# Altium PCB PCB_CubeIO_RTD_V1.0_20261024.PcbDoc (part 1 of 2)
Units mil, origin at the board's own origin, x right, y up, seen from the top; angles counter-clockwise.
Board outline 9739 x 8533 mil, 4 copper layers (TopLayer, GND, VCC, BottomLayer); 78 components, 50 nets, 272 pads, 89 vias.
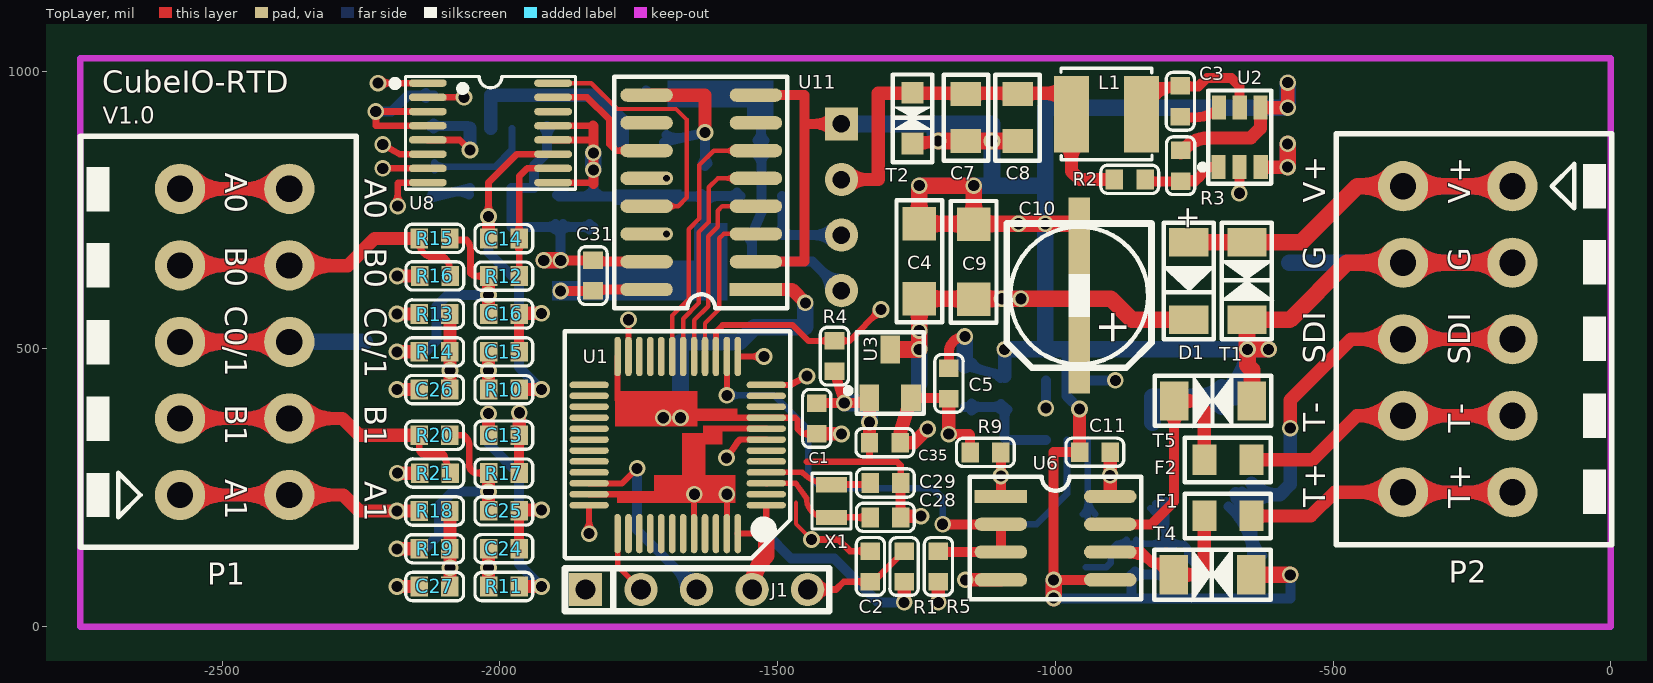
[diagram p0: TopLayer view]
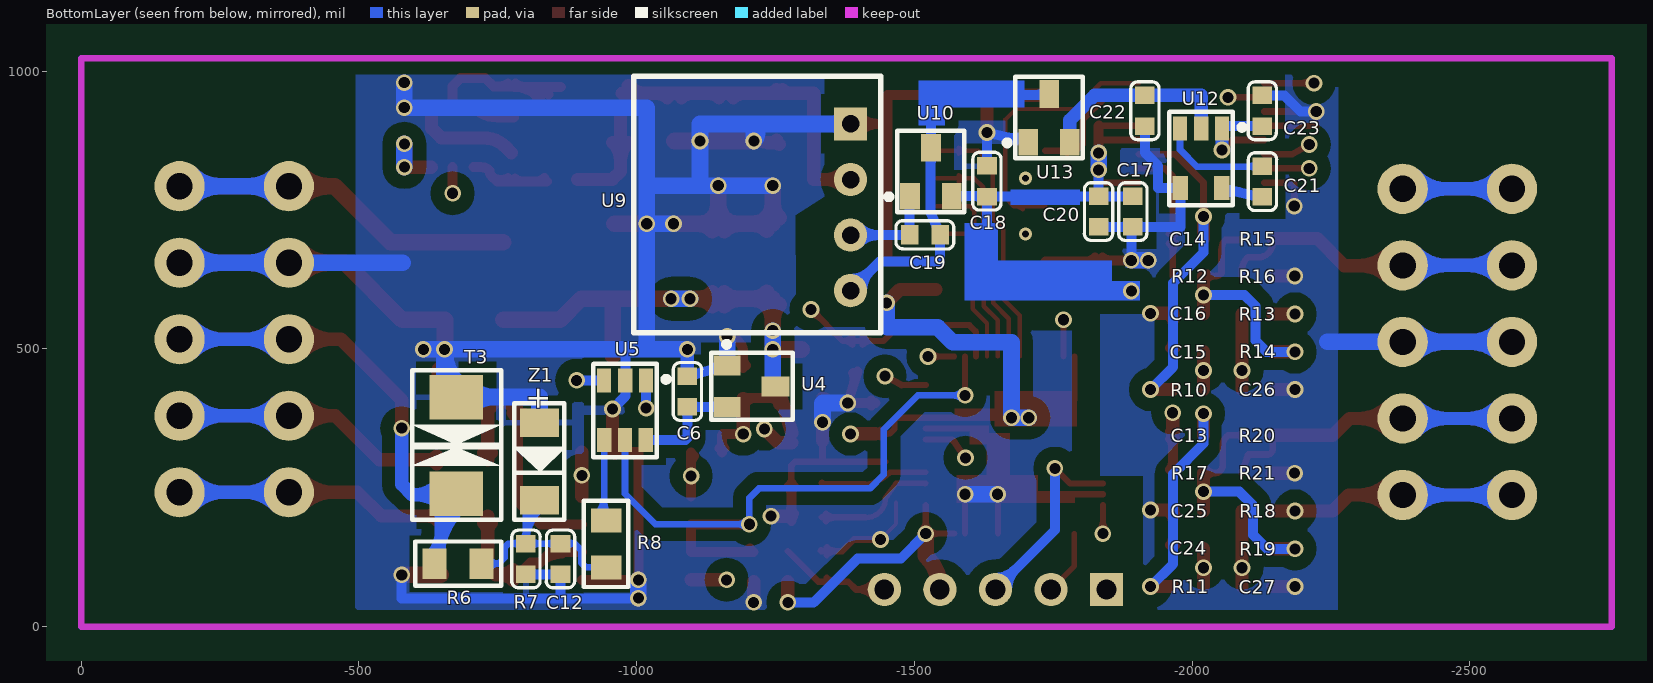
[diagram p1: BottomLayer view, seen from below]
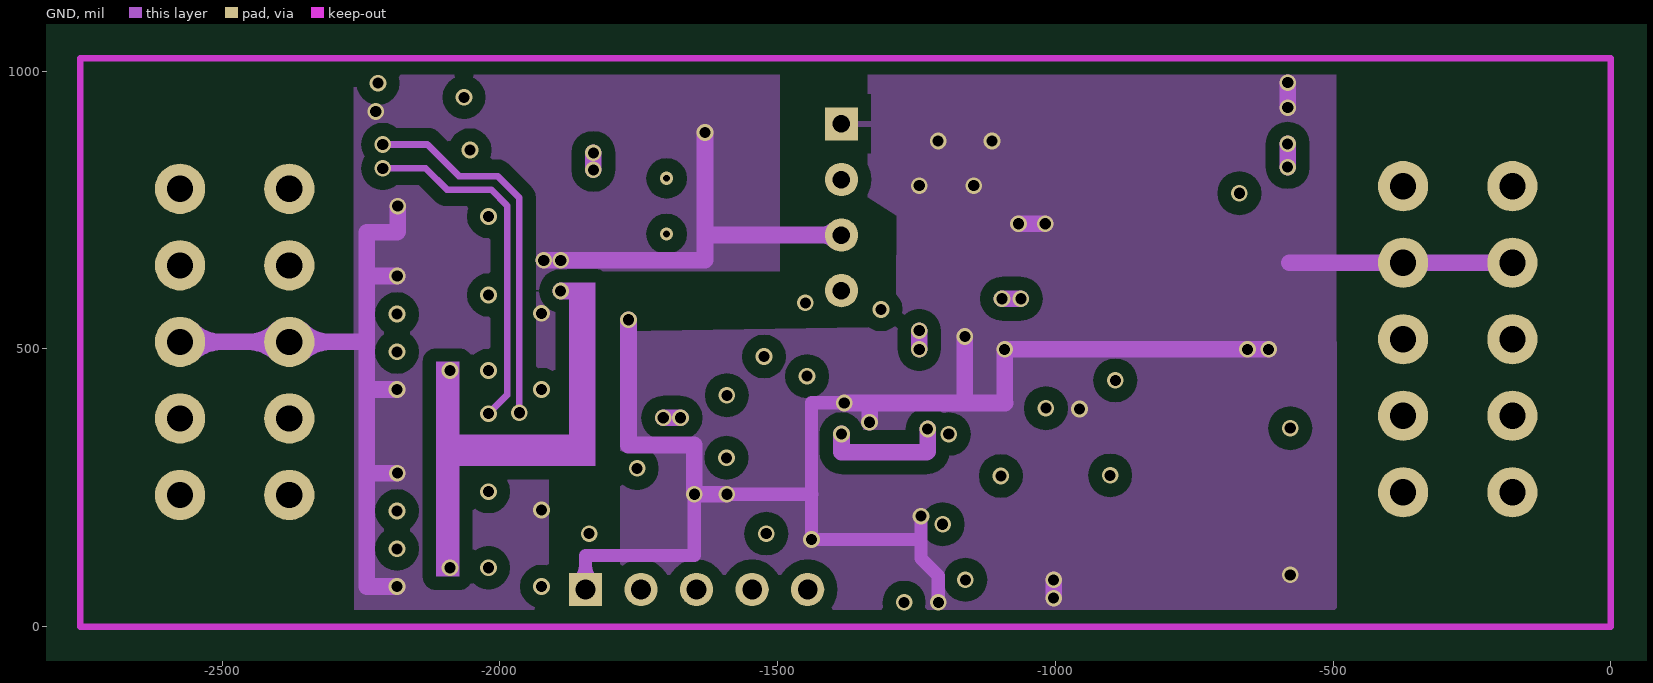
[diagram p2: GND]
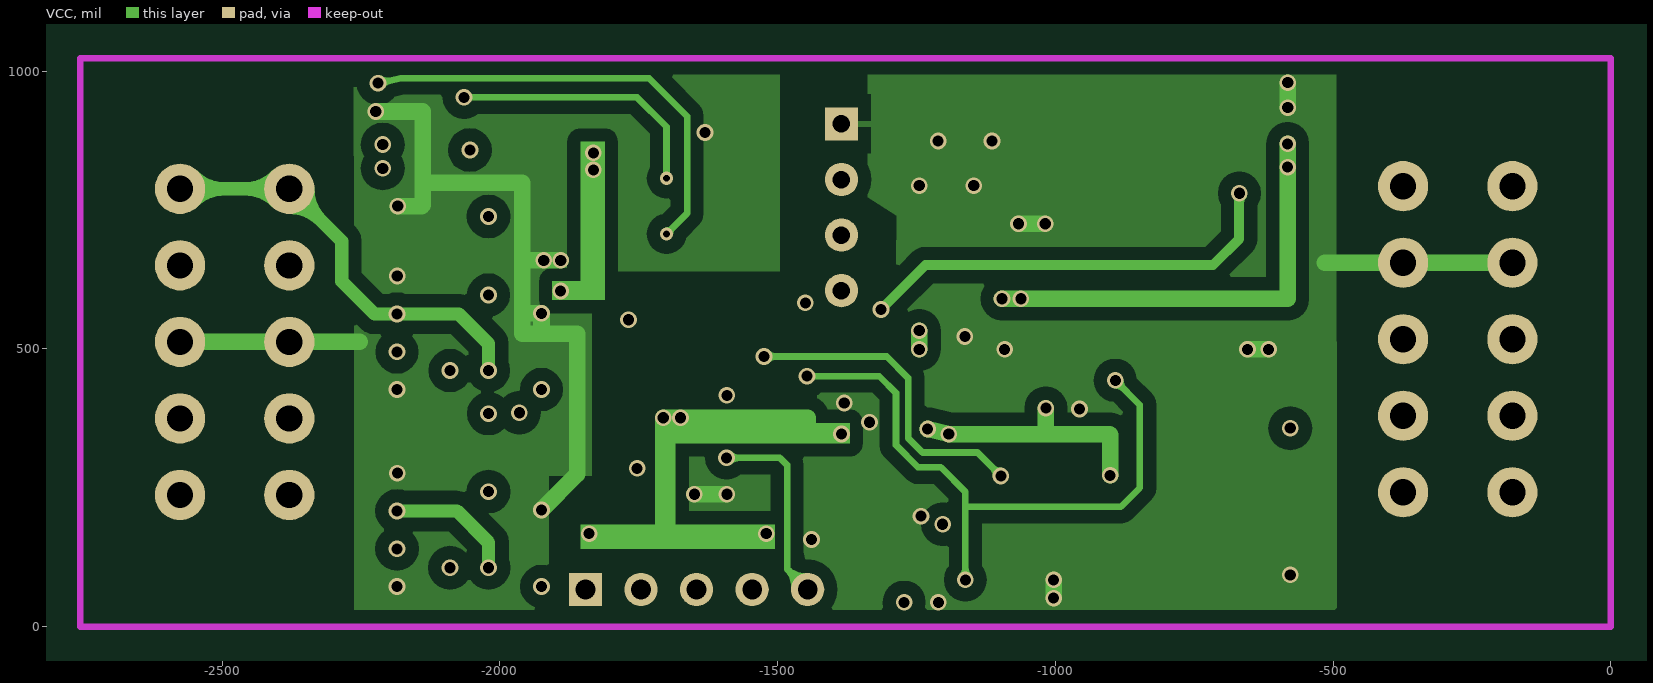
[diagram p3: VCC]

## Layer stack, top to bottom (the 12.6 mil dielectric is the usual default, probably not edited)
TopLayer: signal copper 1.4
Dielectric: core 12.6, FR-4, Dk 4.8
GND: signal copper 1.4
Dielectric: prepreg 12.6, FR-4, Dk 4.8
VCC: signal copper 1.4
Dielectric: core 12.6, FR-4, Dk 4.8
BottomLayer: signal copper 1.4

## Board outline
-5100.31,4111.96 4638.69,4111.96 4638.69,-4391.04 -5100.31,-4391.04 -5100.31,4111.96 -5070.31,4141.96

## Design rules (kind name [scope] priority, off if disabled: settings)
Clearance [All] p1: gap=24
PolygonConnect Via [IsVia] p1: connectstyle=Direct reliefconductorwidth=10 reliefentries=4 polygonreliefangle="90 Angle"
PolygonConnect [All] p2: connectstyle=Relief reliefconductorwidth=10 reliefentries=4 polygonreliefangle="90 Angle"
RoutingLayers [All] p1: top layer_v5=TRUE mid layer 1_v5=FALSE mid layer 2_v5=FALSE bottom layer_v5=TRUE
RoutingPriority [All] p1: routingpriority=4
RoutingVias [All] p1: holewidth=20 width=30 viastyle="Through Hole" minholewidth=20 minwidth=30 maxholewidth=20 maxwidth=30
SilkscreenOverComponentPads [All] p1: minsilkscreentomaskgap=10
SolderMaskExpansion [All] p1: expansion=4
TestPointUsage [All] p1: valid=0 allowmultiple=FALSE
Testpoint [All] p1: side=15 testpointundercomponent=TRUE minsize=40 maxsize=100 preferedsize=60 minholesize=20 maxholesize=40 preferedholesize=32 testpointgrid=1 style=1023 order=0-112345678
Width [All] p1: maxlimit=236.22 minlimit=6 preferedwidth=8
21 further rules are at their usual default settings.

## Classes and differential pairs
component class AI: C13 C14 C15 C16 C17 C18 C19 C20 C21 C22 C23 C24 C25 C26 C27 C31 P1 R10 R11 R12 R13 R14 R15 R16 R17 R18 R19 R20 R21 U8 U9 U10 U11 U12 U13
component class CPU: 5 5.1K 6 BT1 C1 C2 C3 C4 C5 C6 C7 C8 C9 C10 C11 C12 C28 C29 C35 COM D1 D18 D19 F1 F2 J1 JTAG1 L1 L3 P2 P6 P7 P8 PWR PWR1 Q8 R1 R2 R3 R4 R5 R6 R7 R8 R9 RUN SW6 SW7 T1 T2 T3 T4 T5 U1 U2 U3 U4 U5 U6 X1 X2 X3 Z1
component class ATTACH: ATT1 ATT2 ATT3 ATT4 ATT5 ATT6 ATT7 ATT8 ATT9

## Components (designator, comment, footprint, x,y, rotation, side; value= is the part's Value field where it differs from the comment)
C1 "100nf/50V" RC0603(1) -1429.96,347.87 r90 top
C2 "100nf/50V" RC0603(1) -1333.38,81.28 r90 top
C3 "100nf/50V" RC0603(1) -774.59,972.87 r270 top
C4 "10uf/50V" RC1206 -1244.96,590.27 r90 top
C5 "10uf/25V" RC0603(1) -1191.96,410.85 r90 top
C6 "10uf/25V" RC0603(1) -1090.96,396.27 r90 bottom
C7 "22uf/16V" RC0805 -1160.96,958.87 r270 top
C8 "22uf/16V" RC0805 -1067.96,958.87 r270 top
C9 "10uf/50V" RC1206 -1146.96,589.27 r90 top
C10 "47uf/50V" SMD-EC-F6.3 -956.96,488.27 r90 top
C11 "100nf/50V" RC0603(1) -955.96,314.27 r0 top
C12 "220pf/50V" RC0603(1) -863.25,148.78 r270 bottom
C13 "10nf/50V" RC0603(1) -2020,345 r0 top
C14 "10nf/50V" RC0603(1) -2020,699 r0 top
C15 "100nf/50V" RC0603(1) -2020,495.19 r0 top
C16 "100nf/50V" RC0603(1) -2020,563.3 r0 top
C17 "10uf/25V" RC0603(1) -1893.72,774.38 r270 bottom
C18 "100nf/50V" RC0603(1) -1631,829 r270 bottom
C19 "10uf/25V" RC0603(1) -1546,705 r0 bottom
C20 "10uf/25V" RC0603(1) -1832,774.38 r270 bottom
C21 "10uf/25V" RC0603(1) -2126.29,774.08 r90 bottom
C22 "10uf/25V" RC0603(1) -1914.63,901.8 r90 bottom
C23 "10uf/25V" RC0603(1) -2126.75,955.8 r270 bottom
C24 "100nf/50V" RC0603(1) -2020,140.64 r0 top
C25 "100nf/50V" RC0603(1) -2020,208.75 r0 top
C26 "100nf/50V" RC0603(1) -2144.5,427.08 r0 top
C27 "100nf/50V" RC0603(1) -2144.5,72.53 r0 top
C28 "6pf(+/-0.25pf)/50V,COG" RC0603(1) -1278.96,196.27 r180 top
C29 "6pf(+/-0.25pf)/50V,COG" RC0603(1) -1278.96,258.27 r180 top
C31 "100nf/50V" RC0603(1) -1832,659 r270 top
C35 "10uf/25V" RC0603(1) -1279.96,330.87 r180 top
D1 "IN5819WS" SOD-123 -759.96,692.27 r270 top
F1 "自恢复保险丝50mA/60V" RC0805 -646.96,199.27 r180 top
F2 "自恢复保险丝50mA/60V" RC0805 -646.96,300.27 r180 top
J1 "单排针,5P" SIP-5(1) -1845.96,66.87 r180 top
L1 "10uH" SMD_L4.0-W4.0_FNR40XXS -907.96,922.87 r180 top
P1 "接线焊接焊盘" KC-2604P-3.5A-5P（快接侧出线直针,淘宝:宇宙悍将旗舰店） -2576,237 r90 top locked
P2 "外部接线焊盘" KC-2604P-3.5A-5P（快接侧出线直针,淘宝:宇宙悍将旗舰店） -177,793 r270 top locked
R1 "10K,1%" RC0603(1) -1271.96,135.27 r270 top
R2 "200K,1%" RC0603(1) -838.96,804.87 r180 top
R3 "62K,1%" RC0603(1) -773.96,856.87 r270 top
R4 "200K,1%" RC0603(1) -1397.96,459.87 r90 top
R5 "10K,1%" RC0603(1) -1210.96,81.27 r90 top
R6 "510ohm,1%" RC0805 -720.96,113.27 r0 bottom
R7 "200K,1%" RC0603(1) -800.25,94.78 r90 bottom
R8 "510ohm,1%" RC0805 -944.96,191.27 r270 bottom
R9 "5.1K,1%" RC0603(1) -1098.96,313.27 r180 top
R10 "2K,0.1%" RC0603(1) -2020,427.08 r0 top
R11 "2K,0.1%" RC0603(1) -2020,72.53 r0 top
R12 "2K,0.1%" RC0603(1) -2020,631.41 r0 top
R13 "20K,0.1%" RC0603(1) -2090.44,562.42 r180 top
R14 "20K,0.1%" RC0603(1) -2090.44,494.31 r180 top
R15 "300ohm,0.1%" RC0603(1) -2090.44,698.64 r180 top
R16 "20K,0.1%" RC0603(1) -2090,631 r180 top
R17 "2K,0.1%" RC0603(1) -2020,276.86 r0 top
R18 "20K,0.1%" RC0603(1) -2090.44,207.87 r180 top
R19 "20K,0.1%" RC0603(1) -2090.44,139.76 r180 top
R20 "300ohm,0.1%" RC0603(1) -2090.44,344.09 r180 top
R21 "20K,0.1%" RC0603(1) -2089.95,276 r180 top
T1 "SMF28CA" SOD-123-TVS -654.96,692.27 r270 top
T2 "GBLC05C" SOD-323-ESD-GBLCxx/UDD32CxxL01(1) -1257,961.1 r270 top
T3 "SMBJ28CA" "DO-214AA(SMB) -TVS" -674.96,239.27 r90 bottom
T4 "SMF6.5CA" SOD-123-TVS -786.96,93.27 r0 top
T5 "SMF6.5CA" SOD-123-TVS -785.96,406.27 r0 top
U1 "STM32L072CZT7" LQFP48_N -1679.96,326.87 r180 top
U2 "AP63200WU-7(ADJ)" SOT23-6(WIDEPAD) -705.96,827.27 r0 top
U3 "HT7533S" SOT23-3(1) -1334.96,411.87 r0 top
U4 "HT7550S" SOT23-3(1) -1162.96,470.27 r270 bottom
U5 "74LVC1T45DBVR" SOT23-6(WIDEPAD) -1016.96,443.27 r0 bottom
U6 "TP8485E-SR" SO-8-150mil -1097.96,234.27 r0 top
U8 "ADS1220IPWR" TSSOP-16_L5.0-W4.4-P0.65-LS6.4-BL -2017,889 r270 top
U9 "B0303S-1WR2(德旭电子)" MORSUN_B_S_1W-LAY -1385,905 r270 bottom
U10 "AP2210N-3.3TRG1" SOT23-3(1) -1492,775 r180 bottom
U11 "PAI-141U31" SO-16 -1539,607 r180 top
U12 "TPS60400DBVR" SOT23-5(WIDEPAD) -2054,897 r0 bottom
U13 "AP2210N-2.5TRE1" SOT23-3(1) -1705,872 r180 bottom
X1 "32.768kHz" OSC-2012-2P-SMD -1402.96,225.87 r270 top
Z1 "MMSZ4693(7.5V稳压管)" SOD-123 -824.96,367.27 r270 bottom

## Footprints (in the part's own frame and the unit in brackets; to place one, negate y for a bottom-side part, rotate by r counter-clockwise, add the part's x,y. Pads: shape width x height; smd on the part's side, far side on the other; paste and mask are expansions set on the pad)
"DO-214AA(SMB) -TVS" [mil]
  rect 80x96 smd: 1(0,0) 2(174,0)
  silkscreen extent -47,-82 222,80
KC-2604P-3.5A-5P（快接侧出线直针,淘宝:宇宙悍将旗舰店） [mm] "淘宝pokerface0411订单号: 5057329177195112327,宇宙悍将旗舰店"
  round 2.3 hole 1.2: 1(0,0) 1(0,-5) 2(3.5,-5) 2(3.5,0) 3(7,-5) 3(7,0) 4(10.5,-5) 4(10.5,0) 5(14,-5) 5(14,0)
  silkscreen extent -2.4,-8.05 16.4,4.55
LQFP48_N [mm] "Thin QFP, 48-Leads, Body 7x7mm, Pitch 0.5mm, IPC Medium Density"
  oval 1.8x0.3 smd: 1(-4.05,2.75) 2(-4.05,2.25) 3(-4.05,1.75) 4(-4.05,1.25) 5(-4.05,0.75) 6(-4.05,0.25) 7(-4.05,-0.25) 8(-4.05,-0.75) 9(-4.05,-1.25) 10(-4.05,-1.75) 11(-4.05,-2.25) 12(-4.05,-2.75) 25(4.05,-2.75) 26(4.05,-2.25) 27(4.05,-1.75) 28(4.05,-1.25) 29(4.05,-0.75) 30(4.05,-0.25) 31(4.05,0.25) 32(4.05,0.75) 33(4.05,1.25) 34(4.05,1.75) 35(4.05,2.25) 36(4.05,2.75)
  oval 0.3x1.8 smd: 13(-2.75,-4.05) 14(-2.25,-4.05) 15(-1.75,-4.05) 16(-1.25,-4.05) 17(-0.75,-4.05) 18(-0.25,-4.05) 19(0.25,-4.05) 20(0.75,-4.05) 21(1.25,-4.05) 22(1.75,-4.05) 23(2.25,-4.05) 24(2.75,-4.05) 37(2.75,4.05) 38(2.25,4.05) 39(1.75,4.05) 40(1.25,4.05) 41(0.75,4.05) 42(0.25,4.05) 43(-0.25,4.05) 44(-0.75,4.05) 45(-1.25,4.05) 46(-1.75,4.05) 47(-2.25,4.05) 48(-2.75,4.05)
  silkscreen extent -5.16,-5.21 5.16,5.18
MORSUN_B_S_1W-LAY [mil]
  rect 60x60 hole 31.5: 1(0,0)
  round 60 hole 31.5: 2(100,0) 3(200,0) 4(300,0)
  silkscreen extent -86,-390 376,55
OSC-2012-2P-SMD [mm]
  rect 0.7x1.4 smd: 1(-0.75,0) 2(0.75,0)
  silkscreen extent -1.27,-0.89 1.27,0.89
RC0603(1) [mm]
  rect 0.8x0.9 smd: 1(-0.013,-0.007) 2(1.387,-0.007)
  silkscreen extent -0.64,-0.66 2.01,0.64
RC0805 [mm]
  rect 1.1x1.4 smd: 1(0,0) 2(2.15,0)
  silkscreen extent -0.89,-1.02 3.05,1.02
RC1206 [mil] "1/4W 3.2X1.6"
  rect 60x60 smd: 1(0,0) 2(135,0)
  silkscreen extent -42,-41 177,41
SIP-5(1) [mil]
  rect 60x60 hole 35.43: 1(0,0)
  round 60 hole 35.43: 2(-100,0) 3(-200,0) 4(-300,0) 5(-400,0)
  silkscreen extent -439,-38 37,39
SMD-EC-F6.3 [mm]
  rect 3.5x1 smd: 1(0,0) 2(5.475,0)
  silkscreen extent -0.56,-3.31 6.04,3.31
SMD_L4.0-W4.0_FNR40XXS [mm]
  rect 1.6x3.5 smd: 1(-1.6,0) 2(1.6,0)
  silkscreen extent -2.08,-2.1 2.08,2.1
SO-8-150mil [mm]
  rect 2.4x0.61 smd: 1(0,0)
  oval 2.4x0.61 smd: 2(0,-1.27) 3(0,-2.54) 4(0,-3.81) 5(5,-3.81) 6(5,-2.54) 7(5,-1.27) 8(5,0)
  silkscreen extent -1.42,-4.7 6.43,0.89
SO-16 [mm]
  rect 2.4x0.61 smd: 1(0,0)
  oval 2.4x0.61 smd: 2(0,-1.27) 3(0,-2.54) 4(0,-3.81) 5(0,-5.08) 6(0,-6.35) 7(0,-7.62) 8(0,-8.89) 9(5,-8.89) 10(5,-7.62) 11(5,-6.35) 12(5,-5.08) 13(5,-3.81) 14(5,-2.54) 15(5,-1.27) 16(5.004,0)
  silkscreen extent -1.42,-9.73 6.48,0.85
SOD-123 [mm]
  rect 1.3x1.8 smd: 1(0,0) 2(3.556,0)
  silkscreen extent -0.89,-1.22 4.44,1.22
SOD-123-TVS [mm]
  rect 1.3x1.8 smd: 1(0,0) 2(3.556,0)
  silkscreen extent -0.89,-1.24 4.44,1.24
SOD-323-ESD-GBLCxx/UDD32CxxL01(1) [mm]
  rect 1x1 smd: 1(0,0) 2(2.32,0)
  silkscreen extent -0.84,-0.91 3.17,0.9
SOT23-3(1) [mm]
  rect 0.9x1.2 smd: 1(0,0) 2(1.905,0)
  rect 0.9x1.27 smd: 3(0.965,2.21)
  silkscreen extent -1.09,-0.74 2.49,3
SOT23-5(WIDEPAD) [mm]
  rect 0.65x1.1 smd: 1(0,0) 2(0.95,0) 3(1.925,0)
  rect 0.7x1.1 smd: 4(1.912,2.723) 5(0.012,2.723)
  silkscreen extent -1.04,-0.76 2.41,3.51
SOT23-6(WIDEPAD) [mm]
  rect 0.65x1.1 smd: 1(0,0) 2(0.95,0) 3(1.925,0) 4(1.912,2.723) 5(0.965,2.718) 6(0.012,2.723)
  silkscreen extent -0.86,-0.76 2.41,3.51
TSSOP-16_L5.0-W4.4-P0.65-LS6.4-BL [mil]
  oval 13.5x68.17 smd paste+2: 1(-89.57,-112.82) 2(-63.98,-112.82) 3(-38.39,-112.82) 4(-12.79,-112.82) 5(12.8,-112.82) 6(38.39,-112.82) 7(63.98,-112.82) 8(89.57,-112.82) 9(89.57,112.83) 10(63.98,112.83) 11(38.39,112.83) 12(12.8,112.83) 13(-12.79,112.83) 14(-38.39,112.83) 15(-63.98,112.83) 16(-89.57,112.83)
  silkscreen extent -101,-178 101,153

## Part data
C1 C2 C3 C11 C15 C16 C18 C24 C25 C26 C27 C31: library part CAP, "电容,100nf/50V,贴片,0603"
C4 C9: library part CAPACITOR_POL, "电容,10uf/50V,贴片,1206"
C5: library part ELECTRO1, "电容,10uf/25V,贴片,0805"
C6 C19 C20 C35: library part CAP, "电容,10uf/25V,贴片,0805"
C7 C8: library part ELECTRO1, "电容,22uf/16V,贴片,0805"
C10: library part CAPACITOR_POL, "电解电容,47uf/50V,贴片,D6.3L5.4"
C12: library part CAP, "电容,220pf/50V,贴片,0603"
C13 C14: library part CAP, "电容,10nf/50V,贴片,0603"
C17 C21 C22 C23: library part CAP, "电容,10uf/25V,贴片,0603"
C28 C29: library part CAP, "电容,6pf(+/-0.25pf)/50V,COG,贴片,0603"
D1: library part DIODE, "肖特基二极管,IN5819WS,贴片,SOD-123(1206)"
F1 F2: library part FUSE, "自恢复保险丝,自恢复保险丝50mA/60V,贴片,1206"
J1: library part "Header 5", "插针,单排针,直插,2.54MM间距,针高11MM,5P"
L1: library part INDUCTOR, "功率电感,10uH,20%,FHD4020S-100MT,贴片,SMD,4*4*2mm"
P1 P2: library part MHDR1X5, "Header, 5-Pin"
R1: library part RES_1, "电阻,10K,1%,贴片,0603"
R2 R4 R7: library part RESISTOR, "电阻,200K,1%,贴片,0603"
R3: library part RESISTOR, "电阻,62K,1%,贴片,0603"
R5: library part RESISTOR, "电阻,10K,1%,贴片,0603"
R6 R8: library part RESISTOR, "电阻,510ohm,1%,贴片,0805"
R9: library part RESISTOR, "电阻,5.1K,1%,贴片,0603"
R10 R11 R12 R17: library part RESISTOR, "电阻,2K,0.1%,贴片,0603"
R13 R14 R16 R18 R19 R21: library part RESISTOR, "电阻,20K,0.1%,贴片,0603"
R15 R20: library part RESISTOR, "电阻,300ohm,0.1%,贴片,0603"
T1 T3: library part TVS, "抗雷击二极管,SMF28CA,贴片,SOD-123"
T2: library part TVS, "抗雷击二极管,GBLC05C,贴片,SOD-323"
T4 T5: library part TVS, "抗雷击二极管,SMF6.5CA,贴片,SOD-123"
U1: library part STM32L051C8T6
U2: library part SCT2332(DC/DC), "电源,AP63200WU-7(ADJ),贴片,TSOT23-6L"
U3: library part HT7530S(UMW友台半导体), "电源,ME6203A33M3G(LDO,40V输入,3.3V输出),贴片,SOT-23"
U4: library part HT7530S(UMW友台半导体), "电源,ME6203A50M3G(LDO,40V输入,5V输出),贴片,SOT-23"
U5: library part 74LVC1T45, "74系列,74LVC1T45DBVR,贴片,SOT-23-6"
U6: library part MAX485, "RS485通讯,TP8485E-SR,贴片,SO-8"
U8: "AD转换器,ADS1220IPWR(24位AD转换),贴片,TSSOP-16"
U9: library part MORSUN_B0505S_1W, "电源DCDC,B0303S-1WR2(德旭电子),直插,SIP"
U10: library part HT7530S(UMW友台半导体), "电源,AP2210N-3.3TRG1(DIODES美台),贴片,SOT-23"
U11: "光耦,PAI-141U31,贴片,SO-16"
U12: library part TPS60400, "电源,TPS60400DBVR,贴片,SOT-23-5"
U13: library part HT7530S(UMW友台半导体), "电源,AP2210N-2.5TRE1(DIODES美台),贴片,SOT-23"
X1: library part XTAL, "晶振,SC-20S(32.768kHz,20PPM,7pF, Seiko精工),贴片,SMD-2012-2P"
Z1: library part ZENER, "稳压二极管,MMSZ4693(7.5V稳压管),贴片,SOD-123"

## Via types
v1: diameter 30, hole 20, TopLayer to BottomLayer, 87 vias
v2: diameter 24, hole 12, TopLayer to BottomLayer, 2 vias

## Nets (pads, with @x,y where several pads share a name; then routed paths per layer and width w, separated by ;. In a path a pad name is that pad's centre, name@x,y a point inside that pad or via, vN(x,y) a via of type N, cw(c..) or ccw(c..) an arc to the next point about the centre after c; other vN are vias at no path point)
+3V5: C7.1 C8.1 L1.2 R2.2 T2.1 U9.2 | length 1426.5
  TopLayer w24: U9.2@-1385,805 -1319,805 -1319,960 -1318.9,960.1 -1257,960.1 L1.2@-974,960.1 ; L1.2@-970.95,922.87 -970.95,819.95 -956.16,805.16 R2.2@-893.58,805.16 ; -1341.54,805 cw(c-1341.54,848.46) -1372.27,817.73 ccw(c-1341.54,848.46) -1341.54,805 ; -1341.54,805 ccw(c-1341.54,761.54) -1372.27,792.27 cw(c-1341.54,761.54) -1341.54,805 ; -970.95,838.4 cw(c-923.88,838.4) -957.16,871.69 ccw(c-923.88,838.4) -970.95,838.4 ; -970.95,838.4 ccw(c-1018.02,838.4) -984.74,871.69 cw(c-1018.02,838.4) -970.95,838.4 ; -1277.97,960.1 ccw(c-1277.97,982.07) -1262.43,966.54 cw(c-1277.97,982.07) -1277.97,960.1 ; T2.1@-1251.57,966.54 ccw(c-1236.03,982.07) -1236.03,960.1 cw(c-1236.03,982.07) T2.1@-1251.57,966.54 ; -1193.14,960.1 cw(c-1193.14,932.6) -1173.69,952.05 ccw(c-1193.14,932.6) -1193.14,960.1 ; C7.1@-1148.23,952.05 cw(c-1128.78,932.6) -1128.78,960.1 ccw(c-1128.78,932.6) C7.1@-1148.23,952.05 ; -1100.14,960.1 cw(c-1100.14,932.6) -1080.69,952.05 ccw(c-1100.14,932.6) -1100.14,960.1 ; C8.1@-1055.23,952.05 cw(c-1035.78,932.6) -1035.78,960.1 ccw(c-1035.78,932.6) C8.1@-1055.23,952.05 ; -1018.43,960.1 ccw(c-1018.43,1007.76) -984.74,974.06 cw(c-1018.43,1007.76) -1018.43,960.1 ; -1017.6,960.1 cw(c-1017.6,913.62) -984.74,946.49 ccw(c-1017.6,913.62) -1017.6,960.1
+5V: C6.1 U4.2 U5.6 | length 368.3
  BottomLayer w18: U4.2@-1162.96,395.27 -1162.46,395.78 C6.1@-1091.25,395.78 -1091.25,339.33 ; -1087.98,336.06 U5.6@-1016.49,336.06 ; -1109.51,395.78 cw(c-1109.51,379.49) -1097.99,391.01 ccw(c-1109.51,379.49) -1109.51,395.78 ; -1109.51,395.78 ccw(c-1109.51,412.07) -1097.99,400.55 cw(c-1109.51,412.07) -1109.51,395.78 ; -1091.25,379.49 cw(c-1074.96,379.49) -1086.48,391.01 ccw(c-1074.96,379.49) -1091.25,379.49 ; -1091.25,379.49 ccw(c-1107.54,379.49) -1096.02,391.01 cw(c-1107.54,379.49) -1091.25,379.49 ; U4.2@-1150.89,389.11 cw(c-1134.8,373.02) -1134.8,395.78 ccw(c-1134.8,373.02) U4.2@-1150.89,389.11 ; U4.2@-1150.89,401.44 ccw(c-1137.22,415.1) -1137.22,395.78 cw(c-1137.22,415.1) U4.2@-1150.89,401.44
+24V: C4.1 C9.1 C10.1 D1.2 U2.3 U3.3 U4.3 | length 2907.4
  TopLayer w24: U2.3@-630.16,827.27 v1(-581.73,827.27)
  TopLayer w30: U3.3@-1296.96,498.87 -1245.36,498.87 v1(-1244.96,499.27) ; v1@-1244.96,501.27 C4.1@-1244.96,590.27 -1031.96,590.27 -899.96,590.27 -861.96,552.27 -836.96,552.27 D1.2@-759.96,552.27 ; C10.1@-956.96,488.27 -956.96,587.31 -954,590.27 ; v1(-581.73,827.27) v1(-581.73,869.27) ; -1244.96,554.06 cw(c-1208.75,554.06) C4.1@-1234.35,579.67 ; -1244.96,554.06 ccw(c-1281.17,554.06) -1255.57,579.67 cw(c-1281.17,554.06) -1244.96,554.06 ; -1244.96,554.06 cw(c-1208.75,554.06) C4.1@-1234.35,579.67 ; C4.1@-1234.35,579.67 cw(c-1208.75,554.06) -1208.75,590.27 ; C4.1@-1234.35,579.67 cw(c-1208.75,554.06) -1208.75,590.27 ; -1208.75,590.27 cw(c-1208.75,626.49) -1234.35,600.88 ccw(c-1208.75,626.49) -1208.75,590.27 ; -1185.59,590.27 cw(c-1185.59,550.65) -1157.57,578.67 ccw(c-1185.59,550.65) -1185.59,590.27 ; -1180.76,590.27 ccw(c-1180.76,623.07) -1157.57,599.88 cw(c-1180.76,623.07) -1180.76,590.27 ; C9.1@-1136.35,578.67 cw(c-1108.33,550.65) -1108.33,590.27 ccw(c-1108.33,550.65) C9.1@-1136.35,578.67 ; C9.1@-1136.35,599.88 ccw(c-1113.16,623.07) -1113.16,590.27 cw(c-1113.16,623.07) C9.1@-1136.35,599.88
  GND w30: v1(-1244.96,499.27) v1(-1244.96,532.87) ; v1(-1096,590.27) v1(-1062,590.27) ; v1(-581.73,827.27) v1(-581.73,869.27)
  VCC w30: v1(-1244.96,499.27) v1(-1244.96,532.87) ; -587.27,590.27 v1(-1096,590.27) -581.73,590.27 v1(-581.73,827.27) v1(-581.73,869.27)
  BottomLayer w30: U4.3@-1244.96,437.27 v1(-1244.96,499.27) v1(-1244.96,532.87) ; v1(-1096,590.27) v1(-1062,590.27) ; v1(-581.73,827.27) v1(-581.73,869.27)
+24X: D1.1 P2.1 T1.1 | length 1740
  TopLayer w30: D1.1@-759.96,692.27 T1.1@-654.96,692.27 -556.73,692.27 -456,793 P2.1@-177,793 ; -446.94,793 cw(c-446.94,719.91) -395.26,771.59 ccw(c-446.94,719.91) -446.94,793 ; -446.94,793 ccw(c-446.94,866.09) -395.26,814.41 cw(c-446.94,866.09) -446.94,793 ; -300.76,793 cw(c-300.76,866.09) -352.44,814.41 ccw(c-300.76,866.09) -300.76,793 ; -300.76,793 ccw(c-300.76,719.91) -352.44,771.59 cw(c-300.76,719.91) -300.76,793 ; -250.09,793 cw(c-250.09,719.91) -198.41,771.59 ccw(c-250.09,719.91) -250.09,793 ; -250.09,793 ccw(c-250.09,866.09) -198.41,814.41 cw(c-250.09,866.09) -250.09,793
  BottomLayer w30: P2.1@-373.85,793 P2.1@-177,793 ; P2.1@-352.44,771.59 cw(c-300.76,719.91) -300.76,793 cw(c-300.76,866.09) P2.1@-352.44,814.41 ; P2.1@-198.41,771.59 ccw(c-250.09,719.91) -250.09,793 ccw(c-250.09,866.09) P2.1@-198.41,814.41
A: F1.2 T4.1 U6.6 | length 680.4
  TopLayer w18: U6.6@-901.11,134.27 -844.96,134.27 -825.96,115.27 ; T4.1@-786.96,93.27 -808.96,115.27 -825.96,115.27 ; -825.96,115.27 cw(c-825.96,91.04) -802.81,98.21 ccw(c-825.96,91.04) -825.96,115.27 ; U6.6@-865.87,131.27 cw(c-865.87,73.56) -825.06,114.37 ccw(c-865.87,73.56) U6.6@-865.87,131.27 ; U6.6@-864.99,131.41 cw(c-856.05,102.28) -834.51,123.82 ccw(c-856.05,102.28) U6.6@-864.99,131.41
  TopLayer w24: T4.1@-786.96,93.27 -745.96,93.27 -731.61,107.63 F1.2@-731.61,199.27 F1.2@-730.37,198.04 ; -754.15,93.27 cw(c-754.15,126.08) -777.35,102.88 ccw(c-754.15,126.08) -754.15,93.27 ; -754.15,93.27 ccw(c-754.15,60.46) -777.35,83.66 cw(c-754.15,60.46) -754.15,93.27 ; -731.61,170.06 cw(c-708.3,170.06) -724.78,186.54 ccw(c-708.3,170.06) -731.61,170.06 ; -731.61,170.06 ccw(c-754.91,170.06) -738.43,186.54 cw(c-754.91,170.06) -731.61,170.06
A0: C15.1 P1.5 R10.1 R13.2 | length 2545.5
  TopLayer w24: P1.5@-2576,788.18 P1.5@-2379.15,788.18 ; P1.5@-2552.47,764.65 cw(c-2495.67,707.85) -2495.67,788.18 cw(c-2495.67,868.52) P1.5@-2552.47,811.71 ; P1.5@-2402.68,764.65 ccw(c-2459.48,707.85) -2459.48,788.18 ccw(c-2459.48,868.52) P1.5@-2402.68,811.71 ; v1(-2185.23,562.71) R13.2@-2145.06,562.71 ; R10.1@-2020.5,426.79 C15.1@-2020.5,494.9
  VCC w24: P1.5@-2576,788.18 P1.5@-2379.15,788.18 ; P1.5@-2359.18,788.18 P1.5@-2379.15,788.18 ; v1(-2020.5,461) -2020.5,509.5 -2073.71,562.71 v1(-2185.23,562.71) -2225.71,562.71 -2285,622 -2285,694.03 P1.5@-2379.15,788.18 ; -2495.67,788.18 cw(c-2495.67,868.52) -2552.47,811.71 ccw(c-2495.67,868.52) -2495.67,788.18 ; -2495.67,788.18 ccw(c-2495.67,707.85) -2552.47,764.65 cw(c-2495.67,707.85) -2495.67,788.18 ; -2459.48,788.18 cw(c-2459.48,707.85) -2402.68,764.65 ccw(c-2459.48,707.85) -2459.48,788.18 ; -2459.48,788.18 ccw(c-2459.48,868.52) -2402.68,811.71 cw(c-2459.48,868.52) -2459.48,788.18 ; -2322.34,731.38 cw(c-2265.54,788.18) -2345.87,788.18 ccw(c-2265.54,788.18) -2322.34,731.38 ; -2322.34,731.38 ccw(c-2379.15,674.57) -2379.15,754.91 cw(c-2379.15,674.57) -2322.34,731.38
  BottomLayer w24: P1.5@-2576,788.18 P1.5@-2379.15,788.18 ; P1.5@-2552.47,764.65 cw(c-2495.67,707.85) -2495.67,788.18 cw(c-2495.67,868.52) P1.5@-2552.47,811.71 ; P1.5@-2402.68,764.65 ccw(c-2459.48,707.85) -2459.48,788.18 ccw(c-2459.48,868.52) P1.5@-2402.68,811.71
A1: C24.1 P1.1 R11.1 R18.2 | length 1951.1
  TopLayer w24: P1.1@-2576,237 -2282,237 -2253.16,208.16 v1(-2185.23,208.16) R18.2@-2145.06,208.16 ; R11.1@-2020.5,72.24 C24.1@-2020.5,140.35 ; -2495.67,237 cw(c-2495.67,317.33) -2552.47,260.53 ccw(c-2495.67,317.33) -2495.67,237 ; -2495.67,237 ccw(c-2495.67,156.67) -2552.47,213.47 cw(c-2495.67,156.67) -2495.67,237 ; -2459.48,237 cw(c-2459.48,156.67) -2402.68,213.47 ccw(c-2459.48,156.67) -2459.48,237 ; -2459.48,237 ccw(c-2459.48,317.33) -2402.68,260.53 cw(c-2459.48,317.33) -2459.48,237 ; -2298.82,237 cw(c-2298.82,317.33) -2355.62,260.53 ccw(c-2298.82,317.33) -2298.82,237 ; -2298.82,237 ccw(c-2298.82,156.67) -2355.62,213.47 cw(c-2298.82,156.67) -2298.82,237
  VCC w24: v1(-2185.23,208.16) -2077.16,208.16 -2020.5,151.5 v1(-2020.5,106)
  BottomLayer w24: P1.1@-2576,237 P1.1@-2379.15,237 ; P1.1@-2552.47,213.47 cw(c-2495.67,156.67) -2495.67,237 cw(c-2495.67,317.33) P1.1@-2552.47,260.53 ; P1.1@-2402.68,213.47 ccw(c-2459.48,156.67) -2459.48,237 ccw(c-2459.48,317.33) P1.1@-2402.68,260.53
ADC_CS: U8.2 U11.12 | length 544.8
  TopLayer w12: U8.2@-2129.82,952.98 v1(-2064.63,952.98)
  VCC w12: v1(-2064.63,952.98) -1752.98,952.98 -1700,900 v2(-1700,807)
ADC_DIN: U8.16 U11.13 | length 547.1
  TopLayer w8: U8.16@-1904.17,978.57 -1835.57,978.57 -1789,932 -1683,932 -1664,913 -1664,772 -1679,757 U11.13@-1735.85,757 ; -1681.29,757 cw(c-1681.29,776.31) -1694.95,762.66 ccw(c-1681.29,776.31) -1681.29,757 ; -1681.29,757 ccw(c-1681.29,737.69) -1694.95,751.34 cw(c-1681.29,737.69) -1681.29,757
ADC_DOUT_DRDY: U8.15 U11.11 | length 279.4
  TopLayer w12: U8.15@-1904.17,952.98 -1842.98,952.98 -1803,913 -1803,868.92 -1791.08,857 U11.11@-1735.85,857 ; -1785.58,857 cw(c-1785.58,842.51) -1775.34,852.76 ccw(c-1785.58,842.51) -1785.58,857 ; -1785.58,857 ccw(c-1785.58,871.49) -1775.34,861.24 cw(c-1785.58,871.49) -1785.58,857
ADC_SCLK: U8.1 U11.14 | length 1084.9
  TopLayer w12: v1(-2219.57,978.57) U8.1@-2129.82,978.57 ; -2197.84,978.57 cw(c-2197.84,1000.3) -2213.21,984.93 ccw(c-2197.84,1000.3) -2197.84,978.57 ; -2197.84,978.57 ccw(c-2197.84,956.84) -2213.21,972.21 cw(c-2197.84,956.84) -2197.84,978.57
  VCC w12: v1(-2219.57,978.57) -2178,987.43 -1731.42,987.43 -1663,919 -1663,744 v2(-1700,707) ; -2198.32,983.1 cw(c-2202.85,1004.35) -2214.67,986.12 ccw(c-2202.85,1004.35) -2198.32,983.1 ; -2198.32,983.1 ccw(c-2193.79,961.85) -2212.02,973.67 cw(c-2193.79,961.85) -2198.32,983.1 ; -1689.76,717.24 cw(c-1700,727.49) -1700,713 ccw(c-1700,727.49) -1689.76,717.24 ; -1689.76,717.24 ccw(c-1679.51,707) -1694,707 cw(c-1679.51,707) -1689.76,717.24
AGND: C15.2 C16.2 C17.2 C18.1 C19.2 C20.2 C22.1 C23.1 C24.2 C25.2 C26.1 C27.1 C31.1 P1.3 R16.2 R21.2 U8.3 U8.4 U8.8 U9.3 U10.1 U11.9 U11.15 U12.4 U13.1 | length 8497.7
  TopLayer w12: v1@-2224,927 v1(-2223.61,927.39) ; v1(-2184,757) -2184,798.43 -2183,799.43 U8.8@-2129.82,799.43 ; U8.4@-2129.82,901.79 -2223.21,901.79 -2223.21,926.99 v1(-2223.61,927.39) ; U8.3@-2129.82,927.39 v1(-2223.61,927.39) ; -2184,778.73 cw(c-2205.73,778.73) -2190.36,763.36 ccw(c-2205.73,778.73) -2184,778.73 ; -2184,778.73 ccw(c-2162.27,778.73) -2177.64,763.36 cw(c-2162.27,778.73) -2184,778.73
  TopLayer w18: C24.2@-1965.38,140.35 C25.2@-1965.38,208.46 ; C15.2@-1965.38,494.9 C16.2@-1965.38,563.01 ; v1(-1890.5,659.5) C31.1@-1832.29,659.5 -1829.79,657 U11.15@-1735.85,657 ; -1965.38,190.19 cw(c-1949.09,190.19) -1960.61,201.72 ccw(c-1949.09,190.19) -1965.38,190.19 ; -1965.38,190.2 ccw(c-1981.67,190.2) -1970.15,201.72 cw(c-1981.67,190.2) -1965.38,190.2 ; -1965.38,544.74 cw(c-1949.09,544.74) -1960.61,556.26 ccw(c-1949.09,544.74) -1965.38,544.74 ; -1965.38,544.75 ccw(c-1981.67,544.75) -1970.15,556.26 cw(c-1981.67,544.75) -1965.38,544.75 ; -1850.55,659.5 cw(c-1850.55,643.21) -1839.03,654.73 ccw(c-1850.55,643.21) -1850.55,659.5 ; -1850.55,659.5 ccw(c-1850.55,675.79) -1839.03,664.27 cw(c-1850.55,675.79) -1850.55,659.5 ; C24.2@-1970.15,147.09 ccw(c-1981.67,158.6) -1965.38,158.6 cw(c-1981.67,158.6) C24.2@-1970.15,147.09 ; C15.2@-1970.15,501.64 ccw(c-1981.67,513.15) -1965.38,513.15 cw(c-1981.67,513.15) C15.2@-1970.15,501.64 ; -1965.38,158.61 ccw(c-1949.09,158.61) -1960.61,147.09 cw(c-1949.09,158.61) -1965.38,158.61 ; -1965.38,513.16 ccw(c-1949.09,513.16) -1960.61,501.64 cw(c-1949.09,513.16) -1965.38,513.16 ; C31.1@-1825.55,664.27 ccw(c-1808,681.82) -1808,657 cw(c-1808,681.82) C31.1@-1825.55,664.27
  TopLayer w24: v1(-2185.17,72.24) C27.1@-2145,72.24 ; v1(-2185.17,426.79) C26.1@-2145,426.79 ; v1(-2184.79,631.29) R16.2@-2144.62,631.29 ; v1(-2184.73,276.29) R21.2@-2144.57,276.29 ; C25.2@-1965.44,210 v1(-1925.28,210) ; C16.2@-1965.44,564 v1(-1925.28,564) ; U11.9@-1735.85,957 -1631,957 -1630.71,956.29 v1(-1630.71,889.71)
  TopLayer w30: P1.3@-2576,512.59 P1.3@-2379.15,512.59 ; P1.3@-2554.59,491.18 cw(c-2502.91,439.5) -2502.91,512.59 cw(c-2502.91,585.68) P1.3@-2554.59,534 ; P1.3@-2400.56,491.18 ccw(c-2452.24,439.5) -2452.24,512.59 ccw(c-2452.24,585.68) P1.3@-2400.56,534 ; v1(-1921,659.5) v1(-1890.5,659.5)
  GND w30: P1.3@-2576,512.59 -2240.59,512.59 -2240,512 ; -2240,271 -2234.71,276.29 v1(-2184.73,276.29) ; -2240,425 -2238.21,426.79 v1(-2185.17,426.79) ; -2240,626 -2234.71,631.29 v1(-2184.79,631.29) ; v1(-2185.17,72.24) -2239.76,72.24 -2240,72 -2240,710 -2185,710 -2184,711 v1(-2184,757) ; v1(-1921,659.5) v1(-1890.5,659.5) -1631.21,659.5 -1630.71,659.99 -1630.71,735 ; v1(-1630.71,889.71) -1630.71,735 ; U9.3@-1385,705 -1630.71,705 -1630.71,735 ; -2502.91,512.59 cw(c-2502.91,585.68) -2554.59,534 ccw(c-2502.91,585.68) -2502.91,512.59 ; -2502.91,512.59 ccw(c-2502.91,439.5) -2554.59,491.18 cw(c-2502.91,439.5) -2502.91,512.59 ; -2452.24,512.59 cw(c-2452.24,439.5) -2400.56,491.18 ccw(c-2452.24,439.5) -2452.24,512.59 ; -2452.24,512.59 ccw(c-2452.24,585.68) -2400.56,534 cw(c-2452.24,585.68) -2452.24,512.59 ; -2306.06,512.59 cw(c-2306.06,585.68) -2357.74,534 ccw(c-2306.06,585.68) -2306.06,512.59 ; -2306.06,512.59 ccw(c-2306.06,439.5) -2357.74,491.18 cw(c-2306.06,439.5) -2306.06,512.59 ; -1421.21,705 cw(c-1421.21,668.79) -1395.61,694.39 ccw(c-1421.21,668.79) -1421.21,705 ; -1421.21,705 ccw(c-1421.21,741.21) -1395.61,715.61 cw(c-1421.21,741.21) -1421.21,705
  VCC w30: P1.3@-2576,512.59 -2252.59,512.59 ; v1(-2223.61,927.39) -2139,927.39 -2139,759 -2141,757 v1(-2184,757) ; -2139,797 -2136.57,799.43 -1960,799.43 -1960,658.87 ; -1960,563 -1959,564 v1(-1925.28,564) -1925.28,529.72 -1928,527 ; v1(-1925.28,210) -1861,274.28 -1861,527 -1960,527 -1960,658.87 ; v1(-1890.5,659.5) -1958.5,659.5 -1960,658.87
  BottomLayer w18: v1(-2223.61,927.39) -2195,927.39 -2166.09,956.3 C23.1@-2118.46,956.3 ; C22.1@-1914.92,901.3 -1914.92,853.38 -1939,829.3 -1939,789.58 -1939.21,789.79 U12.4@-1978.73,789.79 -1979,789.52 -1979,720 -1978.77,719.77 C17.2@-1893.43,719.77 ; v1(-1890.5,659.5) -1890.5,716.84 C17.2@-1893.43,719.77 ; C20.2@-1831.71,719.77 C17.2@-1893.43,719.77 ; U13.1@-1705,872 v1(-1630.71,889.71) C18.1@-1630.71,829.5 ; U10.1@-1492,775 -1491.38,774.38 C19.2@-1491.38,705.29 -1491.09,705 U9.3@-1385,705 ; -2144.72,956.3 cw(c-2144.72,940) -2133.2,951.52 ccw(c-2144.72,940) -2144.72,956.3 ; -2144.72,956.3 ccw(c-2144.72,972.59) -2133.2,961.07 cw(c-2144.72,972.59) -2144.72,956.3 ; -1914.92,885.01 cw(c-1898.63,885.01) -1910.15,896.53 ccw(c-1898.63,885.01) -1914.92,885.01 ; -1914.92,885.01 ccw(c-1931.21,885.01) -1919.69,896.53 cw(c-1931.21,885.01) -1914.92,885.01 ; -1911.69,719.77 cw(c-1911.69,703.47) -1900.17,714.99 ccw(c-1911.69,703.47) -1911.69,719.77 ; -1911.69,719.77 ccw(c-1911.69,736.06) -1900.17,724.54 cw(c-1911.69,736.06) -1911.69,719.77 ; -1875.17,719.77 cw(c-1875.17,736.06) -1886.69,724.54 ccw(c-1875.17,736.06) -1875.17,719.77 ; -1875.17,719.77 ccw(c-1875.17,703.47) -1886.69,714.99 cw(c-1875.17,703.47) -1875.17,719.77 ; -1849.97,719.77 cw(c-1849.97,703.47) -1838.45,714.99 ccw(c-1849.97,703.47) -1849.97,719.77 ; -1849.97,719.77 ccw(c-1849.97,736.06) -1838.45,724.54 cw(c-1849.97,736.06) -1849.97,719.77 ; -1630.71,845.79 cw(c-1647,845.79) -1635.48,834.27 ccw(c-1647,845.79) -1630.71,845.79 ; -1630.71,845.79 ccw(c-1614.42,845.79) -1625.94,834.27 cw(c-1614.42,845.79) -1630.71,845.79 ; -1491.38,723.55 cw(c-1507.67,723.55) -1496.15,712.03 ccw(c-1507.67,723.55) -1491.38,723.55 ; -1491.38,723.55 ccw(c-1475.09,723.55) -1486.61,712.03 cw(c-1475.09,723.55) -1491.38,723.55 ; -1435.7,705 cw(c-1435.7,654.3) -1399.85,690.15 ccw(c-1435.7,654.3) -1435.7,705 ; -1435.7,705 ccw(c-1435.7,755.7) -1399.85,719.85 cw(c-1435.7,755.7) -1435.7,705 ; C17.2@-1896.23,714.99 cw(c-1910.05,701.17) -1890.5,701.17 ccw(c-1910.05,701.17) C17.2@-1896.23,714.99 ; U13.1@-1700.43,885.33 ccw(c-1679.14,919.96) -1669.71,880.41 cw(c-1679.14,919.96) U13.1@-1700.43,885.33 ; C19.2@-1486.61,710.06 ccw(c-1474.39,722.28) -1474.39,705 cw(c-1474.39,722.28) C19.2@-1486.61,710.06
  BottomLayer w30: P1.3@-2576,512.59 P1.3@-2379.15,512.59 -2243.59,512.59 ; P1.3@-2554.59,491.18 cw(c-2502.91,439.5) -2502.91,512.59 cw(c-2502.91,585.68) P1.3@-2554.59,534 ; P1.3@-2400.56,491.18 ccw(c-2452.24,439.5) -2452.24,512.59 ccw(c-2452.24,585.68) P1.3@-2400.56,534 ; v1(-1921,659.5) v1(-1890.5,659.5)
AIN0+: C14.1 R10.2 U8.11 | length 697.4
  TopLayer w12: v1@-2020.5,738 -2020.5,799.5 -1969.39,850.61 U8.11@-1904.17,850.61 ; -2020.5,760.23 cw(c-2042.22,760.23) -2026.86,744.87 ccw(c-2042.22,760.23) -2020.5,760.23 ; -2020.5,760.23 ccw(c-1998.77,760.23) -2014.13,744.87 cw(c-1998.77,760.23) -2020.5,760.23
  TopLayer w24: C14.1@-2020.5,698.71 v1@-2020.5,738 ; R10.2@-1965.38,426.79 v1(-1925.21,426.79)
  BottomLayer w18: v1@-2020.5,738 -2020.5,673.73 -1965.44,618.68 -1965.44,467.02 v1(-1925.21,426.79)
  other v1: -2020.5,738.5
AIN0-: C14.2 R12.2 U8.10 | length 394.6
  TopLayer w12: R12.2@-1965.38,631.11 -1965.38,810.64 -1951,825.02 U8.10@-1904.17,825.02 ; -1965.38,724.21 cw(c-1988.91,724.21) -1972.27,707.57 ccw(c-1988.91,724.21) -1965.38,724.21 ; -1965.38,724.22 ccw(c-1941.85,724.22) -1958.49,707.57 cw(c-1941.85,724.22) -1965.38,724.22 ; C14.2@-1972.27,689.85 cw(c-1988.91,673.21) -1965.38,673.21 ccw(c-1988.91,673.21) C14.2@-1972.27,689.85 ; -1965.38,673.2 cw(c-1941.85,673.2) -1958.49,689.85 ccw(c-1941.85,673.2) -1965.38,673.2
AIN1+: C13.1 R11.2 U8.7 | length 1151
  TopLayer w12: v1(-2210.98,825.02) U8.7@-2129.82,825.02
  TopLayer w24: C13.1@-2020.5,344.71 v1(-2020.5,383.5) ; R11.2@-1965.38,72.24 v1(-1925.21,72.24)
  GND w12: v1(-2210.98,825.02) -2133.62,825.02 -2095.34,786.73 -2015.73,786.73 -1987,758 -1987,416.99 v1(-2020.5,383.5)
  BottomLayer w18: v1(-2020.5,383.5) -2020.5,329.5 -1965.44,274.44 -1965.44,112.47 v1(-1925.21,72.24)
AIN1-: C13.2 R17.2 U8.6 | length 1062.2
  TopLayer w12: v1(-2211,868) -2180.61,850.61 U8.6@-2129.82,850.61 ; v1@-1965.38,384.62 v1(-1965,385)
  TopLayer w18: R17.2@-1965.38,276.57 v1@-1965.38,384.62 ; -1965.38,294.82 cw(c-1981.67,294.82) -1970.15,283.31 ccw(c-1981.67,294.82) -1965.38,294.82 ; -1965.38,294.83 ccw(c-1949.09,294.83) -1960.61,283.31 cw(c-1949.09,294.83) -1965.38,294.83 ; -1965.38,326.45 cw(c-1949.09,326.45) -1960.61,337.97 ccw(c-1949.09,326.45) -1965.38,326.45 ; -1965.38,326.45 ccw(c-1981.67,326.45) -1970.15,337.97 cw(c-1981.67,326.45) -1965.38,326.45 ; -1965.38,362.97 cw(c-1981.67,362.97) -1970.15,351.45 ccw(c-1981.67,362.97) -1965.38,362.97 ; -1965.38,362.97 ccw(c-1949.09,362.97) -1960.61,351.45 cw(c-1949.09,362.97) -1965.38,362.97
  TopLayer w24: C13.2@-1965.38,344.71 v1@-1965.38,384.62 ; v1@-1965.38,384.62 cw(c-1965,384.62) v1(-1965,385) ; v1@-1965.38,384.62 cw(c-1965,384.62) v1(-1965,385) ; v1@-1965.38,384.62 cw(c-1965,384.62) v1(-1965,385)
  GND w12: v1(-2211,868) -2130.61,868 -2073.61,811 -2004.42,811 -1965,771.58 v1(-1965,385)
B: F2.2 T5.1 U6.7 | length 766
  TopLayer w18: U6.7@-901.11,184.27 -826.96,184.27 -785.96,225.27 T5.1@-785.96,406.27 ; -785.96,356.38 cw(c-745.91,356.38) -774.23,384.7 ccw(c-745.91,356.38) -785.96,356.38 ; -785.96,356.38 ccw(c-826.01,356.38) -797.69,384.7 cw(c-826.01,356.38) -785.96,356.38
  TopLayer w24: T5.1@-785.96,406.27 -747.96,406.27 -731.61,389.92 F2.2@-731.61,300.27 ; -753.15,406.27 cw(c-753.15,439.08) -776.35,415.88 ccw(c-753.15,439.08) -753.15,406.27 ; -753.15,406.27 ccw(c-753.15,373.46) -776.35,396.66 cw(c-753.15,373.46) -753.15,406.27 ; -731.61,329.49 cw(c-754.91,329.49) -738.43,313.01 ccw(c-754.91,329.49) -731.61,329.49 ; -731.61,329.49 ccw(c-708.3,329.49) -724.78,313.01 cw(c-708.3,329.49) -731.61,329.49
B0: P1.4 R15.2 R16.1 | length 1774.1
  TopLayer w12: R15.2@-2145.06,698.93 -2145.06,691.06 ccw(c-2119,691.06) -2119,665 -2100,665 cw(c-2125.34,639.66) -2089.5,639.66 R16.1@-2089.5,631.29 R16.1@-2089.5,643.37
  TopLayer w24: P1.4@-2576,650.39 P1.4@-2379.15,650.39 -2378.76,650 -2274,650 -2225.07,698.93 R15.2@-2145.06,698.93 ; -2495.67,650.39 cw(c-2495.67,730.72) -2552.47,673.92 ccw(c-2495.67,730.72) -2495.67,650.39 ; -2495.67,650.39 ccw(c-2495.67,570.05) -2552.47,626.86 cw(c-2495.67,570.05) -2495.67,650.39 ; -2459.48,650.39 cw(c-2459.48,570.05) -2402.68,626.86 ccw(c-2459.48,570.05) -2459.48,650.39 ; -2459.48,650.39 ccw(c-2459.48,730.72) -2402.68,673.92 cw(c-2459.48,730.72) -2459.48,650.39 ; P1.4@-2355.62,626.86 cw(c-2299.75,570.98) -2299.75,650 ccw(c-2299.75,570.98) P1.4@-2355.62,626.86 ; P1.4@-2355.62,673.92 ccw(c-2297.88,731.65) -2297.88,650 cw(c-2297.88,731.65) P1.4@-2355.62,673.92
  BottomLayer w24: P1.4@-2576,650.39 P1.4@-2379.15,650.39 ; P1.4@-2552.47,626.86 cw(c-2495.67,570.05) -2495.67,650.39 cw(c-2495.67,730.72) P1.4@-2552.47,673.92 ; P1.4@-2402.68,626.86 ccw(c-2459.48,570.05) -2459.48,650.39 ccw(c-2459.48,730.72) P1.4@-2402.68,673.92
B1: P1.2 R20.2 R21.1 | length 1767.1
  TopLayer w12: R20.2@-2145.06,344.38 -2145.06,319 ccw(c-2136.06,319) -2136.06,310 -2101,310 R21.1@-2089.45,276.29 R21.1@-2089.45,280.71
  TopLayer w24: P1.2@-2574.2,373 P1.2@-2576,374.8 -2283.8,374.8 -2282,373 -2253.38,344.38 R20.2@-2145.06,344.38 ; -2495.67,374.8 cw(c-2495.67,455.13) -2552.47,398.32 ccw(c-2495.67,455.13) -2495.67,374.8 ; -2495.67,374.8 ccw(c-2495.67,294.46) -2552.47,351.27 cw(c-2495.67,294.46) -2495.67,374.8 ; -2459.48,374.8 cw(c-2459.48,294.46) -2402.68,351.27 ccw(c-2459.48,294.46) -2459.48,374.8 ; -2459.48,374.8 ccw(c-2459.48,455.13) -2402.68,398.32 cw(c-2459.48,455.13) -2459.48,374.8 ; -2298.82,374.8 cw(c-2298.82,455.13) -2355.62,398.32 ccw(c-2298.82,455.13) -2298.82,374.8 ; -2298.82,374.8 ccw(c-2298.82,294.46) -2355.62,351.27 cw(c-2298.82,294.46) -2298.82,374.8
  BottomLayer w24: P1.2@-2576,374.8 P1.2@-2379.15,374.8 ; P1.2@-2552.47,351.27 cw(c-2495.67,294.46) -2495.67,374.8 cw(c-2495.67,455.13) P1.2@-2552.47,398.32 ; P1.2@-2402.68,351.27 ccw(c-2459.48,294.46) -2459.48,374.8 ccw(c-2459.48,455.13) P1.2@-2402.68,398.32
CPU_ADC_CS: U1.18 U11.5 | length 476.1
  TopLayer w8: U1.18@-1670.12,486.32 -1670.12,554.51 -1642,582.63 -1642,710.37 -1624,728.37 -1624,791 -1608,807 U11.5@-1539,807 ; -1593.56,807 cw(c-1593.56,787.69) -1579.9,801.34 ccw(c-1593.56,787.69) -1593.56,807 ; -1593.56,807 ccw(c-1593.56,826.31) -1579.9,812.66 cw(c-1593.56,826.31) -1593.56,807
CPU_ADC_DIN: U1.17 U11.4 | length 352.6
  TopLayer w8: U1.17@-1650.43,486.32 -1650.43,551.57 -1625,577 -1625,703 -1608,720 -1608,749 -1600,757 U11.4@-1539,757
CPU_ADC_DOUT_DRDY: U1.19 U11.6 | length 538.3
  TopLayer w8: U1.19@-1689.8,486.32 -1689.8,560.2 -1660,590 -1660,715.63 -1640.88,734.75 -1640.88,831.12 -1615,857 U11.6@-1539,857 ; -1593.56,857 cw(c-1593.56,837.69) -1579.9,851.34 ccw(c-1593.56,837.69) -1593.56,857 ; -1593.56,857 ccw(c-1593.56,876.31) -1579.9,862.66 cw(c-1593.56,876.31) -1593.56,857
CPU_ADC_SCLK: U1.16 U11.3 | length 292.7
  TopLayer w8: U1.16@-1630.75,486.32 -1630.75,546.25 -1605,572 -1605,699 -1597,707 U11.3@-1539,707
CPU_PWR1: R4.2 U1.15 U2.2 | length 1461.4
  TopLayer w11: U1.15@-1611.06,486.32 -1611.06,530.77 -1609.96,531.87 -1598.96,542.87 -1472.96,542.87 -1444.58,514.49 R4.2@-1397.67,514.49 -1370.51,514.49 v1(-1314,571) ; -1424.38,514.49 cw(c-1424.38,489.75) -1406.88,507.24 ccw(c-1424.38,489.75) -1424.38,514.49 ; -1424.38,514.49 ccw(c-1424.38,539.23) -1406.88,521.74 cw(c-1424.38,539.23) -1424.38,514.49 ; -1370.96,514.49 cw(c-1370.96,539.23) -1388.45,521.74 ccw(c-1370.96,539.23) -1370.96,514.49 ; -1370.96,514.49 ccw(c-1370.96,489.75) -1388.45,507.24 cw(c-1370.96,489.75) -1370.96,514.49 ; -1330.22,554.78 cw(c-1314,538.57) -1314,561.5 ccw(c-1314,538.57) -1330.22,554.78 ; -1330.22,554.78 ccw(c-1346.43,571) -1323.5,571 cw(c-1346.43,571) -1330.22,554.78
  TopLayer w18: v1(-668.56,780.27) U2.2@-668.56,827.27
  VCC w18: v1(-1314,571) -1234,651 -716,651 -669,698 -669,779.83 v1(-668.56,780.27) ; -669,764.72 cw(c-653,764.72) -664.32,776.03 ccw(c-653,764.72) -669,764.72
CPU_RXD: R9.1 U1.13 U6.1 | length 946.1
  TopLayer w10: U1.13@-1571.69,486.32 v1(-1524.41,486.32) ; -1548.55,486.32 cw(c-1548.55,462.18) -1531.48,479.25 ccw(c-1548.55,462.18) -1548.55,486.32 ; -1548.55,486.32 ccw(c-1548.55,510.46) -1531.48,493.39 cw(c-1548.55,510.46) -1548.55,486.32
  TopLayer w18: U6.1@-1097.96,234.27 R9.1@-1097.96,313.56 ; R9.1@-1103.24,306.82 cw(c-1115.98,294.08) -1097.96,294.08 ccw(c-1115.98,294.08) R9.1@-1103.24,306.82
  VCC w12: v1(-1524.41,486.32) -1303.41,486.32 -1264.96,447.87 -1264.96,411.87 -1264.96,339.68 -1238.85,313.56 -1140.25,313.56 v1(-1097.96,271.27) ; -1502.68,486.32 cw(c-1502.68,508.05) -1518.04,492.69 ccw(c-1502.68,508.05) -1502.68,486.32 ; -1502.68,486.32 ccw(c-1502.68,464.59) -1518.04,479.96 cw(c-1502.68,464.59) -1502.68,486.32 ; -1113.32,286.64 cw(c-1128.69,271.27) -1106.96,271.27 ccw(c-1128.69,271.27) -1113.32,286.64 ; -1113.32,286.64 ccw(c-1097.96,302) -1097.96,280.27 cw(c-1097.96,302) -1113.32,286.64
